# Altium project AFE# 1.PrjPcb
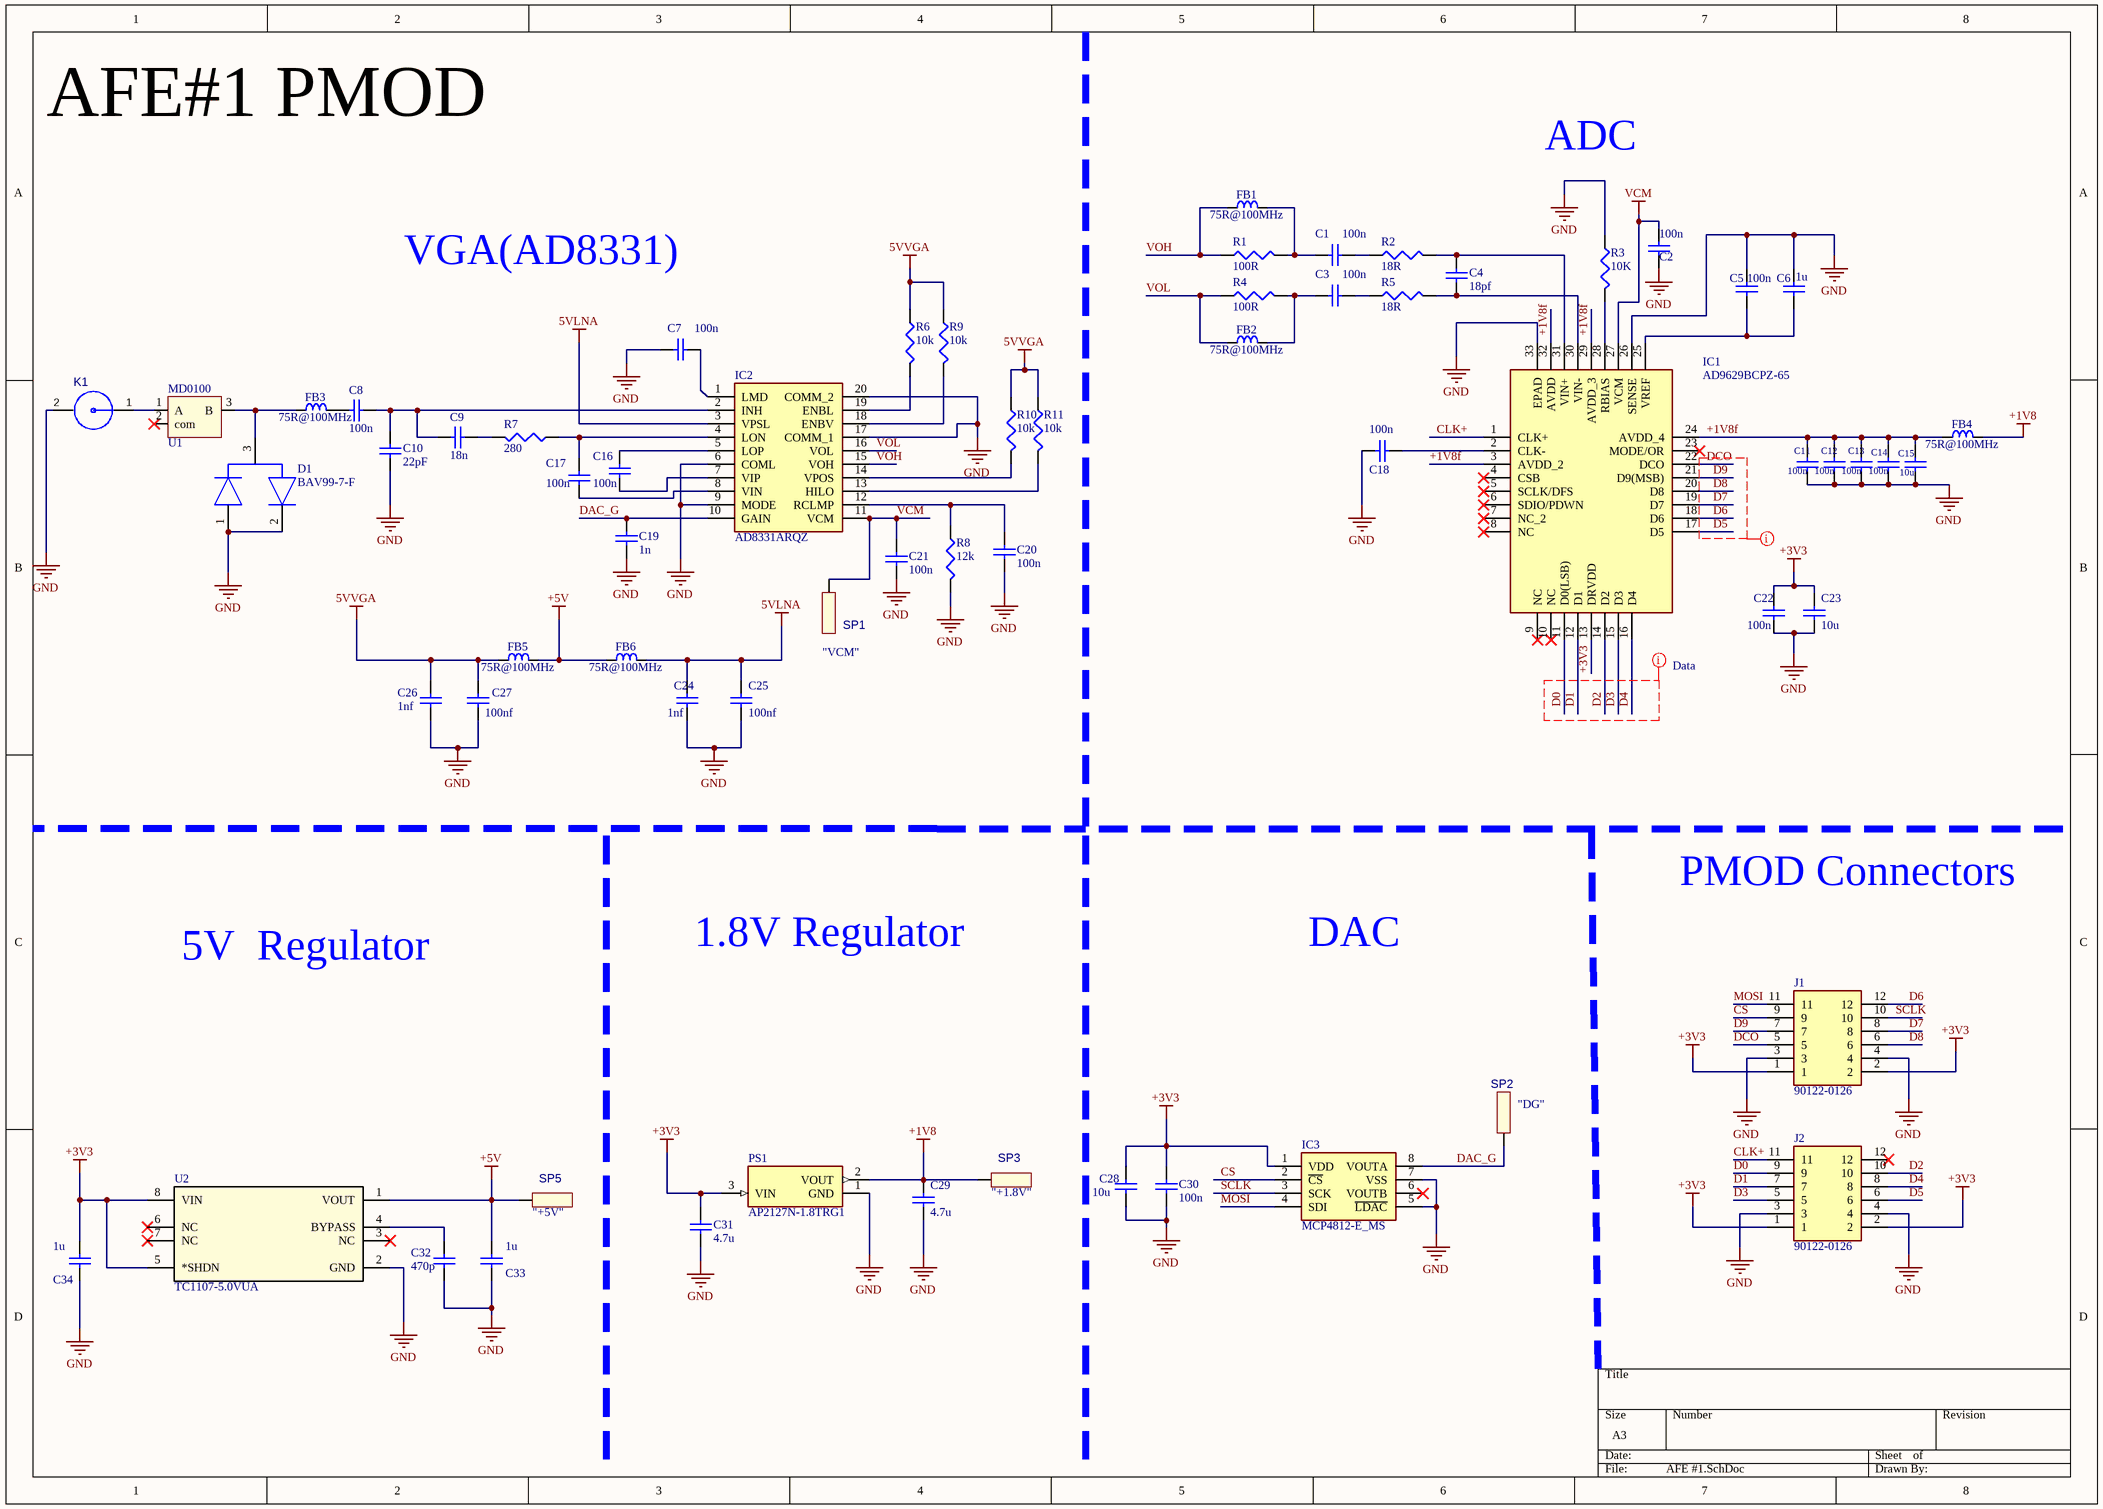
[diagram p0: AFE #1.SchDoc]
1 sheet, 65 parts. Net scope: global (net labels, ports and power ports of the same name join across sheets).
Board file: AFE#1.PcbDoc

## Sheet AFE #1.SchDoc
size A3; PageSetup: Record=PageOptions¦CenterHorizontal=True¦CenterVertical=True¦PrintScale=0.70¦XCorrection=1.00¦YCorrection=1.00¦PrintKind=0¦BorderSize=5000000¦LeftOffset=0¦BottomOffset=0¦Orientation=2¦PaperLength=1000¦PaperWidth=1000¦Scale=100¦PaperSource=7¦PrintQuality=600¦MediaType=1¦DitherType=10¦PrintScaleMode=1¦PaperKind=Letter¦PaperIndex=1

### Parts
C1  value 100n  [0402_C]  (hidden comment: cap0402)
C2  value 100n  [0402_C]  (hidden comment: cap0402)
C3  value 100n  [0402_C]  (hidden comment: cap0402)
C4  value 18pf  [0402_C]  (hidden comment: cap0402)
C5  value 100n  [0402_C]  (hidden comment: cap0402)
C6  value 1u  [SM0603 _3D_cap]  (hidden comment: cap0603)
C7  value 100n  [0402_C]  (hidden comment: cap0402)
C8  value 100n  [0402_C]  (hidden comment: cap0402)
C9  value 18n  [0402_C]  (hidden comment: cap0402)
C10  value 22pF  [0402_C]  (hidden comment: cap0402)
C11  value 100n  [0402_C]  (hidden comment: cap0402)
C12  value 100n  [0402_C]  (hidden comment: cap0402)
C13  value 100n  [0402_C]  (hidden comment: cap0402)
C14  value 100n  [0402_C]  (hidden comment: cap0402)
C15  value 10u  [SM0603 _3D_cap]  (hidden comment: cap0402)
C16  value 100n  [0402_C]  (hidden comment: cap0402)
C17  value 100n  [0402_C]  (hidden comment: cap0402)
C18  value 100n  [0402_C]  (hidden comment: cap0402)
C19  value 1n  [0402_C]  (hidden comment: cap0402)
C20  value 100n  [0402_C]  (hidden comment: cap0402)
C21  value 100n  [0402_C]  (hidden comment: cap0402)
C22  value 100n  [0402_C]  (hidden comment: cap0402)
C23  value 10u  [SM0603 _3D_cap]  (hidden comment: cap0603)
C24  value 1nf  [0402_C]  (hidden comment: cap0402)
C25  value 100nf  [0402_C]  (hidden comment: cap0402)
C26  value 1nf  [0402_C]  (hidden comment: cap0402)
C27  value 100nf  [0402_C]  (hidden comment: cap0402)
C28  value 10u  [SM0603 _3D_cap]  (hidden comment: cap0603)
C29  value 4.7u  [SM0603 _3D_cap]  (hidden comment: cap0603)
C30  value 100n  [0402_C]  (hidden comment: cap0402)
C31  value 4.7u  [SM0603 _3D_cap]  (hidden comment: cap0603)
C32  value 470p  [0402_C]  (hidden comment: cap0402)
C33  value 1u  [SM0603 _3D_cap]  (hidden comment: cap0603)
C34  value 1u  [SM0603 _3D_cap]  (hidden comment: cap0603)
D1  BAV99-7-F  [SOT95P240X120-3N]
FB1  75R@100MHz  [SM0603_3D_res]
FB2  75R@100MHz  [SM0603_3D_res]
FB3  75R@100MHz  [SM0603_3D_res]
FB4  75R@100MHz  [SM0603_3D_res]
FB5  75R@100MHz  [SM0603_3D_res]
FB6  75R@100MHz  [SM0603_3D_res]
IC1  AD9629BCPZ-65  [QFN50P500X500X100-33N]
IC2  AD8331ARQZ  [SOP64P600X175-20N]
IC3  MCP4812-E_MS  [SOP65P490X110-8N]
J1  90122-0126  [HDRRA12W65P254_2X6_1516X250X615P]
J2  90122-0126  [HDRRA12W65P254_2X6_1516X250X615P]
K1  SMA_Edge  [AMPHENOL_132357-11]  (value not drawn)
PS1  AP2127N-1.8TRG1  [SOT89P240X110-3N]
R1  100R  [0402_R]
R2  18R  [0402_R]
R3  10K  [0402_R]
R4  100R  [0402_R]
R5  18R  [0402_R]
R6  10k  [0402_R]
R7  280  [0402_R]
R8  12k  [0402_R]
R9  10k  [0402_R]
R10  10k  [0402_R]
R11  10k  [0402_R]
SP1  value "VCM"  [SolderPad_D1mm _round]  (hidden comment: SolderPad D1mm_round)
SP2  value "DG"  [SolderPad_D1mm _round]  (hidden comment: SolderPad D1mm_round)
SP3  value "+1.8V"  [SolderPad_D1mm _round]  (hidden comment: SolderPad D1mm_round)
SP5  value "+5V"  [SolderPad_D1mm _round]  (hidden comment: SolderPad D1mm_round)
U1  T/R switch  [SOT89-150P409X160-3N]  (value not drawn)
U2  TC1107-5.0VUA  [MSOP8_MC_MCH_]

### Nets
5VLNA: C24.2 C25.2 FB6.2 IC2.3(VPSL)
5VVGA: C26.2 C27.2 FB5.1 R6.1 R9.1 R10.1 R11.1
+1V8: C29.1 FB4.2 PS1.2(VOUT) SP3.1
+3V3: C22.1 C23.1 C28.1 C30.1 C31.2 C34.1 IC1.13(DRVDD) IC3.1(VDD) J1.1 J1.2 J2.1 J2.2 PS1.3(VIN) U2.5(*SHDN) U2.8(VIN)
+5V: C33.1 FB5.2 FB6.1 SP5.1 U2.1(VOUT)
GND: C2.2 C5.1 C6.1 C7.1 C10.1 C11.2 C12.2 C13.2 C14.2 C15.2 C18.2 C19.1 C20.1 C21.2 C22.2 C23.2 C24.1 C25.1 C26.1 C27.1 C28.2 C29.2 C30.2 C31.1 C32.1 C33.2 C34.2 D1.1(ANODE) D1.2(CATHODE) IC1.26(SENSE) IC1.33(EPAD) IC2.6(COML) IC2.9(MODE) IC2.17(COMM_1) IC2.20(COMM_2) IC3.5(~{LDAC}) IC3.7(VSS) J1.3 J1.4 J2.3 J2.4 K1.2 PS1.1(GND) R3.1 R8.2 U2.2(GND)
VCM: C2.1 C21.1 IC1.27(VCM) IC2.11(VCM) SP1.1
+1V8f: C11.1 C12.1 C13.1 C14.1 C15.1 FB4.1 IC1.3(AVDD_2) IC1.24(AVDD_4) IC1.29(AVDD_3) IC1.32(AVDD)
CLK+: IC1.1(CLK+) J2.11
CS: IC3.2(~{CS}) J1.9
D0: IC1.11(D0(LSB)) J2.9
D1: IC1.12(D1) J2.7
D2: IC1.14(D2) J2.10
D3: IC1.15(D3) J2.5
D4: IC1.16(D4) J2.8
D5: IC1.17(D5) J2.6
D6: IC1.18(D6) J1.12
D7: IC1.19(D7) J1.8
D8: IC1.20(D8) J1.6
D9: IC1.21(D9(MSB)) J1.7
DAC_G: C19.2 IC2.10(GAIN) IC3.8(VOUTA) SP2.1
DCO: IC1.22(DCO) J1.5
MOSI: IC3.4(SDI) J1.11
SCLK: IC3.3(SCK) J1.10
VOH: FB1.1 IC2.15(VOH) R1.1
VOL: FB2.1 IC2.16(VOL) R4.1
NetC1_1: C1.1 R2.1
NetC1_2: C1.2 FB1.2 R1.2
NetC3_1: C3.1 R5.1
NetC3_2: C3.2 FB2.2 R4.2
NetC4_1: C4.1 IC1.31(VIN+) R2.2
NetC4_2: C4.2 IC1.30(VIN-) R5.2
NetC5_2: C5.2 C6.2 IC1.25(VREF)
NetC7_2: C7.2 IC2.1(LMD)
NetC8_1: C8.1 FB3.2
NetC8_2: C8.2 C9.2 C10.2 IC2.2(INH)
NetC9_1: C9.1 R7.2
NetC16_1: C16.1 IC2.7(VIP)
NetC16_2: C16.2 IC2.5(LOP)
NetC17_1: C17.1 IC2.8(VIN)
NetC17_2: C17.2 IC2.4(LON) R7.1
NetC18_1: C18.1 IC1.2(CLK-)
NetC20_2: C20.2 IC2.12(RCLMP) R8.1
NetC32_2: C32.2 U2.4(BYPASS)
NetD1_3: D1.3(A/K) FB3.1 U1.3(B)
NetIC1_28: IC1.28(RBIAS) R3.2
NetIC2_13: IC2.13(HILO) R11.2
NetIC2_14: IC2.14(VPOS) R10.2
NetIC2_18: IC2.18(ENBV) R9.2
NetIC2_19: IC2.19(ENBL) R6.2
NetK1_1: K1.1 U1.1(A)

Not connected (* = marked no-connect by the designer): IC1 4(CSB)* 5(SCLK/DFS)* 6(SDIO/PDWN)* 7(NC_2)* 8(NC)* 9(NC)* 10(NC)* 23(MODE/OR)*; IC3 6(VOUTB)*; J2 12*; U1 2(com)*; U2 3(NC)* 6(NC)* 7(NC)*

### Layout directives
net class Data; rule Matched Net Lengths [Tolerance = 20mil]: D0, D1, D2, D3, D4, D5, D6, D7, D8, D9, DCO

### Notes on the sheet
- AFE#1 PMOD
- ADC
- VGA(AD8331)
- (near U1) MD0100
- PMOD Connectors
- 5V  Regulator
- 1.8V Regulator
- DAC

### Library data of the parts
C1-C5 C7-C22 C25 C27 C30 C32 = cap0603: Capacitor  0402 inch
C6 C23 C24 C26 C28 C29 C31 C33 C34 = cap0603: Capacitor  0603 inch
D1 = BAV99-7-F: Diode; Manufacturer_Name: Diodes Inc.
FB1-FB6 = chip inductance 0603: Part Number: IND0805_MURATA_BLM21BB750SN1D; Part Description: SMD EMIFIL Suppression Chip Ferrite Bead; Manufacturer: MURATA; Manufacturer Part Number: BLM21BB750SN1D; Power: 700mA; Resistance: 0.16R; Tolerance: ±25%; Table: Inductors SMD
IC1 = AD9629BCPZ-65: Integrated Circuit; Manufacturer_Name: Analog Devices
IC2 = AD8331ARQZ: Integrated Circuit; Manufacturer_Name: Analog Devices
IC3 = MCP4812-E_MS: Integrated Circuit; Manufacturer_Name: Microchip; Manufacturer_Part_Number: MCP4812-E/MS
J1 J2 = 90122-0126: Connector; Manufacturer_Name: Molex
PS1 = AP2127N-3.3TRG1: Power Supply; Manufacturer_Name: Diodes Inc.
R1 R3 R4 = RC0402FR-0710KL: RES 10K OHM 1/16W 0402 SMD; Power (Watts): 0.063W, 1/16W; .Checked PCB: used
R2 R5 = RC0402FR-0710KL: RES 18 OHM 1/16W 0402 SMD; Power (Watts): 0.063W, 1/16W; .Checked PCB: used
R6 R9-R11 = RC0402FR-0710KL: RES 10K OHM 1/16W 1% 0402 SMD; Resistance (Ohms): 280; Power (Watts): 0.063W, 1/16W; .Checked PCB: used
R7 = RC0402FR-0710KL: RES 280 OHM 1/16W 0402 SMD; Power (Watts): 0.063W, 1/16W; .Checked PCB: used
R8 = RC0402FR-0710KL: RES 12K OHM 1/16W 0402 SMD; Power (Watts): 0.063W, 1/16W; .Checked PCB: used
SP1-SP3 SP5 = SolderPad D1mm_round: for finger touch
U1 = MD0100N8-G
U2 = TC1107-5.0VUA: No Description Available; Mfr_Name: Microchip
